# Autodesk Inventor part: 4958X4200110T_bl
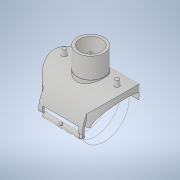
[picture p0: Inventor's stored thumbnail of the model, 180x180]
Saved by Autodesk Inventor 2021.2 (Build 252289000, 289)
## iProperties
Created: 2020-06
Part Number: 4958X4200110T_bl
Material: Generic
Description: Plasson Branch Saddle 200x110
Document SubType Name: Modeling
Designer: KIM
Density: 1 g/cm^3
Appearance: Default
Author: KIM
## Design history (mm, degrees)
derived "4958X4.ipt"
feature "Solid1::4958X4.ipt" dims "ScaleForDerivedMember" = 10
tag "TaggingFeature1"
body "Solid1"
other parameters: "d0" = 295 [user parameter], "d3" = 246.2 [user parameter], "d4" = 111 [user parameter], "d7" = 89 [user parameter], "d9" = 84 [user parameter], "d10" = 0.5 [user parameter], "d11" = 1 [user parameter], "d12" = 27.75 [user parameter], "d13" = 16 [user parameter], "d14" = 8 [user parameter], "d16" = 10 deg [user parameter], "d17" = 10 deg [user parameter], "d19" = 0 [user parameter], "d23" = 0 [user parameter], "d26" = 0 [user parameter], "d27" = 177 [user parameter], "d28" = 0 [user parameter], "d29" = 147.5 [user parameter], "d30" = 0 [user parameter], "d31" = 1 [user parameter], "d32" = 1 [user parameter], "d33" = 19.2 [user parameter], "d34" = 9.6 [user parameter], "d35" = 45 deg [user parameter], "d36" = 147.5 [user parameter], "d37" = 0 [user parameter], "d38" = 5 [user parameter], "d39" = 85 deg [user parameter], "d40" = 27.75 [user parameter], "d41" = 16 [user parameter], "d42" = 107.27273 [user parameter], "d49" = 3 [user parameter], "d50" = 6 [user parameter], "d51" = 5 [user parameter], "d54" = 0 [user parameter], "d57" = 35 deg [user parameter], "d60" = 18.4375 [user parameter], "d61" = 1 [user parameter], "d62" = 90 deg [user parameter], "d63" = 2 [user parameter], "d64" = 0 [user parameter], "d65" = 0 [user parameter], "d68" = 36.875 [user parameter], "d70" = 0.57711 [user parameter], "d71" = 10 deg [user parameter], "d73" = 8.085 [user parameter], "B" = 277 [user parameter], "L" = 295 [user parameter], "LS" = 84 [user parameter], "H1" = 111 [user parameter], "Dt" = 16 [user parameter], "di" = 89 [user parameter], "d72" = 23.1 [user parameter]
